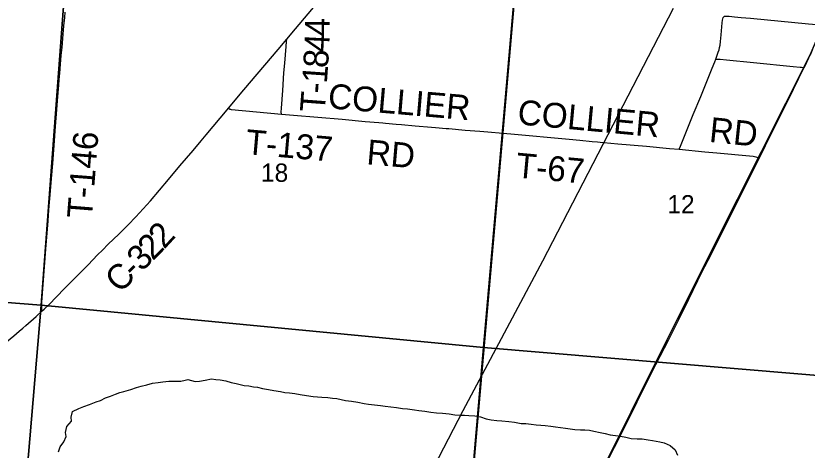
# Model space of a CAD drawing. Extents: x 0 to 1134, y 0 to 440.
# Drawn here: x 843.365 to 845.172, y 357.891 to 358.883 of the extents above; entities that cross this region are included whole.
import ezdxf

# ---------------------------------------------------------------- set-up
doc = ezdxf.new("R2010")
doc.units = 0
for name, color, linetype in [('GM_X_County_Road', 7, 'Continuous'), ('GM_X_County_Road_Text', 7, 'Continuous'), ('GM_X_Minor_River', 7, 'Continuous'), ('GM_X_Rail_Line', 7, 'Continuous'), ('GM_X_Section', 7, 'Continuous'), ('GM_X_Section_Text', 7, 'Continuous'), ('GM_X_Township', 7, 'Continuous'), ('GM_X_Township_Road', 7, 'Continuous'), ('GM_X_Township_Road_Text', 7, 'Continuous'), ('GM_X_Unincorporated', 7, 'Continuous'), ('GM_X_US_Route', 7, 'Continuous')]:
    doc.layers.add(name, color=color, linetype=linetype)

msp = doc.modelspace()

# ---------------------------------------------------------------- linework, layer by layer
at = {"layer": 'GM_X_County_Road'}
for points in [[(843.9834, 358.8296), (844.0036, 358.8536), (844.0814, 358.9466), (844.1134, 358.9847), (844.1856, 359.0702), (844.2276, 359.1201), (844.2299, 359.1229)], [(843.8501, 358.672), (843.8851, 358.7137), (843.9636, 358.8061), (843.9834, 358.8296)], [(843.4247, 358.2091), (843.4294, 358.2133), (843.4406, 358.2241), (843.4755, 358.2595), (843.5131, 358.2978), (843.5301, 358.3147), (843.5515, 358.3373), (843.5624, 358.3483), (843.5757, 358.3613), (843.5997, 358.3845), (843.6213, 358.406), (843.6385, 358.4237), (843.6555, 358.4421), (843.672, 358.4603), (843.7131, 358.5093), (843.7391, 358.5402), (843.7694, 358.5756), (843.788, 358.5978), (843.7995, 358.6112), (843.8153, 358.6303), (843.8472, 358.6685), (843.8501, 358.672)], [(843.0901, 357.9968), (843.0936, 357.9982), (843.1167, 358.0076), (843.1309, 358.0139), (843.1421, 358.0195), (843.1584, 358.0286), (843.1772, 358.0395), (843.2146, 358.0616), (843.2441, 358.0789), (843.2658, 358.091), (843.285, 358.1011), (843.2988, 358.1084), (843.3096, 358.1146), (843.3201, 358.1214), (843.3302, 358.1287), (843.3434, 358.1387), (843.36, 358.1526), (843.3726, 358.1633), (843.3805, 358.1701), (843.3877, 358.1761), (843.411, 358.1966), (843.4247, 358.2091)]]:
    msp.add_lwpolyline(points, dxfattribs=at)
at = {"layer": 'GM_X_Minor_River'}
for points in [[(843.7578, 358.0523), (843.7743, 358.0484), (843.7842, 358.0491), (843.7974, 358.0509), (843.8115, 358.0538), (843.8213, 358.0529), (843.8311, 358.0517), (843.8444, 358.0493), (843.8565, 358.0461), (843.8678, 358.0433), (843.8859, 358.0393), (843.8965, 358.0381), (843.9071, 358.0361), (843.9169, 358.0349), (843.9279, 358.0321), (843.9415, 358.0297), (843.9536, 358.0273), (843.9691, 358.0252), (843.979, 358.0232), (843.9899, 358.022), (844.0017, 358.0204), (844.0138, 358.0187), (844.0285, 358.0159), (844.0436, 358.0139), (844.0535, 358.0134), (844.0637, 358.0125), (844.0769, 358.0112), (844.0875, 358.01), (844.0977, 358.0095), (844.1079, 358.0071), (844.1178, 358.0048), (844.1314, 358.0031), (844.1458, 358.0007), (844.1605, 357.9979), (844.1703, 357.9963), (844.1836, 357.9946), (844.1976, 357.993), (844.2082, 357.9917), (844.221, 357.9901), (844.2343, 357.9884), (844.2479, 357.9868), (844.2589, 357.9855), (844.2751, 357.9835), (844.2853, 357.9818), (844.299, 357.9802), (844.3122, 357.9778), (844.3254, 357.9765), (844.3391, 357.9756), (844.3546, 357.9739), (844.3674, 357.9719), (844.3788, 357.971), (844.389, 357.9709), (844.3992, 357.9704), (844.4129, 357.9696), (844.4261, 357.9671), (844.4389, 357.9632), (844.4499, 357.9608), (844.4627, 357.9592), (844.4745, 357.9579), (844.4904, 357.957), (844.5036, 357.955), (844.5187, 357.9525), (844.5293, 357.9521), (844.5411, 357.9508), (844.5532, 357.9495), (844.5634, 357.9483), (844.5736, 357.9474), (844.5865, 357.9462), (844.5971, 357.9449), (844.6088, 357.9433), (844.6201, 357.9417), (844.6303, 357.94), (844.6413, 357.9388), (844.6538, 357.9379), (844.664, 357.9374), (844.675, 357.9366), (844.6848, 357.9349), (844.6992, 357.9314), (844.7102, 357.929), (844.7222, 357.9266), (844.7344, 357.925), (844.7457, 357.9233), (844.7574, 357.9206), (844.7695, 357.9182), (844.7835, 357.9173), (844.7949, 357.9168), (844.8085, 357.9151), (844.8187, 357.9131), (844.835, 357.9107), (844.8455, 357.9079), (844.8587, 357.9017), (844.8704, 357.8917), (844.8756, 357.8799)], [(843.4622, 357.8872), (843.4657, 357.8992), (843.4746, 357.9105), (843.4796, 357.9222), (843.4779, 357.9317), (843.481, 357.9457), (843.4922, 357.9573), (843.4915, 357.9668), (843.4943, 357.9796), (843.5084, 357.9863), (843.5198, 357.9907), (843.5331, 357.9954), (843.5479, 358.0013), (843.5581, 358.005), (843.5695, 358.0105), (843.5813, 358.0145), (843.5923, 358.0193), (843.6022, 358.0226), (843.6117, 358.0252), (843.6272, 358.0299), (843.6401, 358.0343), (843.6511, 358.0372), (843.664, 358.0404), (843.6769, 358.0441), (843.6898, 358.0458), (843.7004, 358.0472), (843.7144, 358.0485), (843.7288, 358.0487), (843.7416, 358.049), (843.7511, 358.0515), (843.7578, 358.0523)]]:
    msp.add_lwpolyline(points, dxfattribs=at)
at = {"layer": 'GM_X_Rail_Line'}
for points in [[(846.3458, 361.5102), (846.106, 361.002), (846.0456, 360.8726), (845.8559, 360.2141), (845.7851, 360.0449), (845.7229, 359.9444), (845.6533, 359.8622), (845.5758, 359.7804), (845.5564, 359.7595), (845.5217, 359.6718), (845.4977, 359.6064), (845.3993, 359.3625), (845.2065, 358.8608), (845.178, 358.7931), (844.9566, 358.3533), (844.582, 357.6032), (844.3357, 357.1113), (844.0901, 356.6196), (843.8375, 356.1142)], [(843.4365, 356.1484), (843.6778, 356.6167), (843.9649, 357.1678), (844.3862, 357.9816), (844.5681, 358.3237), (844.8668, 358.9004)]]:
    msp.add_lwpolyline(points, dxfattribs=at)
at = {"layer": 'GM_X_Section'}
for points in [[(842.4696, 359.2746), (843.4725, 359.1925), (843.4949, 359.1906), (843.4223, 358.2223), (842.4019, 358.3021)], [(843.4949, 359.1906), (844.4842, 359.101), (844.5175, 359.0975), (844.4326, 358.1255), (843.4223, 358.2223)], [(844.5175, 359.0975), (845.4793, 359.0162), (845.53, 359.0106), (845.441, 358.0413), (844.4326, 358.1255)], [(842.4019, 358.3021), (843.4223, 358.2223), (843.3352, 357.1906), (842.3134, 357.2799)], [(843.4223, 358.2223), (844.4326, 358.1255), (844.3449, 357.1111), (843.3352, 357.1906)], [(844.4326, 358.1255), (845.441, 358.0413), (845.3453, 357.0247), (844.3449, 357.1111)]]:
    msp.add_lwpolyline(points, close=True, dxfattribs=at)
at = {"layer": 'GM_X_Township'}
msp.add_lwpolyline([(844.5185, 359.0983), (844.4766, 358.6156), (844.3467, 357.1313), (844.2974, 356.6008), (844.294, 356.5638), (844.2906, 356.5266), (844.2873, 356.4863), (844.2857, 356.4677), (844.2836, 356.4428), (844.2823, 356.428), (844.281, 356.4093), (844.2785, 356.3747), (844.2775, 356.3623), (844.2757, 356.3375), (844.2748, 356.3251), (844.2737, 356.3127), (844.2722, 356.2941), (844.2671, 356.2257), (844.2625, 356.1667), (844.2571, 356.1015), (844.2565, 356.0936), (843.8425, 356.1236), (843.4392, 356.1543), (843.0091, 356.1875)], dxfattribs=at)
at = {"layer": 'GM_X_Township_Road'}
for points in [[(843.4247, 358.2091), (843.4245, 358.2117), (843.4241, 358.2163), (843.4241, 358.2223), (843.4244, 358.2291), (843.4305, 358.3096), (843.4335, 358.3499), (843.4361, 358.3871), (843.4384, 358.415), (843.4402, 358.4397), (843.4437, 358.4833), (843.4468, 358.5203), (843.449, 358.5458), (843.4531, 358.5973), (843.4547, 358.6208), (843.4562, 358.6402), (843.4578, 358.659), (843.4595, 358.679), (843.461, 358.699), (843.463, 358.7244), (843.4641, 358.7366), (843.4653, 358.7518), (843.4671, 358.7724), (843.4686, 358.7924), (843.4705, 358.811), (843.4723, 358.8313), (843.4747, 358.8604), (843.4764, 358.879), (843.4773, 358.8912)], [(844.9632, 358.7842), (844.9688, 358.7998), (844.9706, 358.8057), (844.9717, 358.8105), (844.9727, 358.8164), (844.9738, 358.8241), (844.9753, 358.8395), (844.9777, 358.8673), (844.9784, 358.8733), (844.9791, 358.8762), (844.9801, 358.879), (844.9812, 358.8806), (844.9828, 358.8819), (844.9842, 358.8824), (844.9866, 358.8826), (844.9932, 358.8822), (845.0054, 358.881), (845.0208, 358.8795), (845.0424, 358.8775), (845.1748, 358.8651), (845.1932, 358.8633), (845.1975, 358.8628), (845.2033, 358.8617), (845.2063, 358.8611)], [(843.9715, 358.6584), (843.9711, 358.6597), (843.9708, 358.6615), (843.9707, 358.6632), (843.9713, 358.6724), (843.9741, 358.7122), (843.9771, 358.7532), (843.9789, 358.7749), (843.982, 358.8128), (843.9829, 358.8242), (843.9834, 358.8296)], [(844.8793, 358.5782), (844.8801, 358.5799), (844.8824, 358.5852), (844.9116, 358.6579), (844.9286, 358.6989), (844.9545, 358.7634), (844.9605, 358.7779), (844.9632, 358.7842)], [(844.9632, 358.7842), (844.9694, 358.7841), (844.9731, 358.7839), (844.9876, 358.7824), (845.0492, 358.7764), (845.14, 358.7676), (845.1556, 358.7661), (845.1587, 358.7657), (845.165, 358.7649)], [(843.8501, 358.672), (843.8523, 358.6709), (843.8537, 358.6702), (843.855, 358.6696), (843.8565, 358.6692), (843.8576, 358.6689), (843.9715, 358.6584)], [(843.9715, 358.6584), (843.9988, 358.6559), (844.1101, 358.6467), (844.1625, 358.6421), (844.1933, 358.6393), (844.2025, 358.6384), (844.2087, 358.6378), (844.2334, 358.6357), (844.2457, 358.6346), (844.2766, 358.6321), (844.3136, 358.6289), (844.3228, 358.6281), (844.3477, 358.626)], [(844.3477, 358.626), (844.3536, 358.6255), (844.3906, 358.6223), (844.4245, 358.6195), (844.4429, 358.6179), (844.4768, 358.6151)], [(844.4768, 358.6151), (844.4947, 358.6136), (844.6279, 358.6011), (844.6527, 358.5988), (844.6805, 358.5962), (844.6929, 358.595), (844.7053, 358.5938), (844.7073, 358.5936)], [(844.7073, 358.5936), (844.7394, 358.5909), (844.8045, 358.5851), (844.8572, 358.5803), (844.8793, 358.5782)], [(844.8793, 358.5782), (844.9378, 358.5727), (844.9657, 358.5703), (845.04, 358.5634), (845.0482, 358.5623), (845.0542, 358.5609), (845.059, 358.5592), (845.0622, 358.5581)]]:
    msp.add_lwpolyline(points, dxfattribs=at)
at = {"layer": 'GM_X_Unincorporated'}
msp.add_lwpolyline([(844.5185, 359.0983), (844.4766, 358.6156), (844.3467, 357.1313), (844.2974, 356.6008)], dxfattribs=at)
at = {"layer": 'GM_X_US_Route'}
for points in [[(845.0622, 358.5581), (845.0681, 358.5698), (845.0766, 358.5871), (845.0955, 358.6248), (845.1148, 358.6631), (845.128, 358.6901), (845.1528, 358.7403), (845.165, 358.7649), (845.167, 358.769), (845.1758, 358.7874), (845.1783, 358.793), (845.1789, 358.7942), (845.1823, 358.8017), (845.1864, 358.8118), (845.1908, 358.8221), (845.2013, 358.848), (845.2063, 358.8611)], [(844.7181, 357.8704), (844.732, 357.8983), (844.7475, 357.9294), (844.7629, 357.96), (844.7835, 358.0016), (844.7971, 358.0287), (844.8165, 358.0675), (844.8363, 358.1061), (844.8547, 358.1423), (844.8784, 358.1893), (844.9012, 358.2358), (844.9222, 358.2785), (844.9382, 358.3108), (844.9533, 358.3399), (845.0153, 358.4644), (845.0355, 358.5043), (845.052, 358.5375), (845.0622, 358.5581)]]:
    msp.add_lwpolyline(points, dxfattribs=at)

# ---------------------------------------------------------------- texts
at = {"layer": 'GM_X_County_Road_Text'}
for s, rotation, p in [('2', 47.1709, (843.7034, 358.3487)), ('2', 45.5088, (843.6776, 358.3224)), ('3', 44.931, (843.6524, 358.2973)), ('C', 44.7144, (843.6025, 358.2478)), ('-', 44.763, (843.6357, 358.2807))]:
    msp.add_text(s, height=0.0568, rotation=rotation, dxfattribs=at).set_placement(p)
at = {"layer": 'GM_X_Section_Text'}
for s, p in [('18', (843.9245, 358.504)), ('12', (844.8524, 358.4318))]:
    msp.add_text(s, height=0.04186, rotation=0, dxfattribs=at).set_placement(p)
at = {"layer": 'GM_X_Township_Road_Text'}
for s, height, rotation, p in [('4', 0.0568, 89.3794, (844.0814, 358.8359)), ('4', 0.0568, 87.1697, (844.0796, 358.7986)), ('8', 0.0568, 86.4224, (844.0774, 358.7629)), ('1', 0.0568, 85.9241, (844.0749, 358.7274)), ('-', 0.0568, 85.7599, (844.0731, 358.704)), ('COLLIER', 0.05682, 355.1285, (844.076, 358.6721)), ('T', 0.0568, 85.7318, (844.07, 358.6616)), ('COLLIER', 0.05682, 354.7032, (844.5088, 358.6354)), ('RD', 0.05682, 354.0424, (844.9464, 358.5954)), ('T-146', 0.05682, 85.5155, (843.5382, 358.4189)), ('T-137', 0.05682, 354.9591, (843.8879, 358.5675)), ('RD', 0.05682, 355.0793, (844.1643, 358.5442)), ('T-67', 0.05682, 354.7793, (844.5048, 358.5141))]:
    msp.add_text(s, height=height, rotation=rotation, dxfattribs=at).set_placement(p)

doc.saveas('drawing.dxf')
